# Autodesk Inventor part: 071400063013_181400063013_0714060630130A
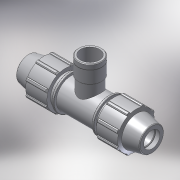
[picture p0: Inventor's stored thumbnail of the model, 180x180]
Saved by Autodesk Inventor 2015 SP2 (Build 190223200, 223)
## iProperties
Created: 2017-02
Part Number: 071400063013_181400063013_0714060630130A
Material: PVC-Piping
Description: PLASSON TEE WITH THREADED FEMALE OFFTAKE 63-1.1/4"-63
Document SubType Name: Modeling
Designer: KIM
Mass: 92.6774 g
Surface Area: 199.44 cm^2
Volume: 66.1981 cm^3
Density: 1.4 g/cm^3
Appearance: Smooth - White
Author: KIM
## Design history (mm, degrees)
derived "07140.ipt"
feature "Solid1::07140.ipt"
feature "Solid2::07140.ipt"
tag "TaggingFeature1"
body "Solid1"
other parameters: "d2" = 63, "d4" = 11.16667, "d5" = 32.16, "d7" = 113, "d11" = 4.46667, "d13" = 120 deg, "d14" = 81.9, "d15" = 12 deg, "d16" = 98.31, "d18" = 3.15, "d19" = 35 deg, "d20" = 17.5 deg, "d21" = 105.09, "d23" = 0, "d25" = 360 deg, "d27" = 2.26, "d33" = 1.26, "d42" = 48.24, "d43" = 3.39, "d46" = 1.89, "d68" = 8.04, "d72" = 95, "d76" = 38.952, "d80" = 1.16856, "d91" = 84.75, "d93" = 113, "d95" = 56.7, "d112" = 27, "d115" = 48.69, "d116" = 135 deg, "d117" = 44.7948, "d118" = 268, "d119" = 56.7, "d121" = 0, "d122" = 34.02, "d124" = 0, "d128" = 0, "d129" = 6.3, "d130" = 8.1, "d131" = 0.3, "d132" = 0.3, "d133" = 48.69, "d_" = 63, "E_" = 113, "A_" = 95, "l_" = 113, "l_2" = 27, "Rp_" = 38.952, "H_" = 268
